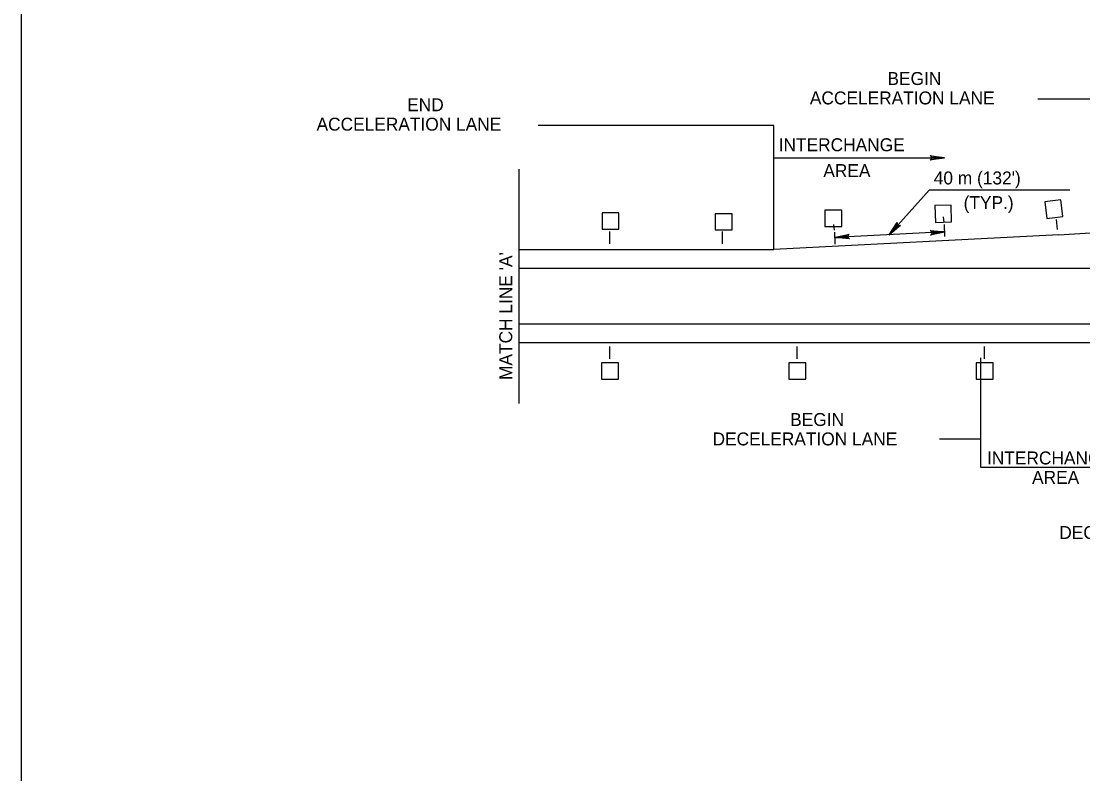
# Model space of a CAD drawing. Extents: x 640253 to 641999, y 298458 to 299646.
# Drawn here: x 641134.3 to 641380.3, y 299301.1 to 299475.5 of the extents above; entities that cross this region are included whole.
import ezdxf

# ---------------------------------------------------------------- set-up
doc = ezdxf.new("R2010")
doc.units = 0
doc.layers.add('1', color=7, linetype='Continuous')
doc.layers.add('2', color=7, linetype='Continuous')

msp = doc.modelspace()

# ---------------------------------------------------------------- linework, layer by layer
at = {"layer": '1'}
msp.add_line((641134.31, 299630.63), (641134.31, 299066.63), dxfattribs=at)
at = {"layer": '2'}
for p, q in [((641394.05, 299457.45), (641369.89, 299457.45)), ((641308.68, 299451.35), (641254.07, 299451.35)), ((641308.68, 299422.63), (641308.68, 299451.35)), ((641308.68, 299443.82), (641348.22, 299443.82)), ((641249.69, 299386.92), (641249.69, 299441.25)), ((641348.12, 299428.88), (641348.03, 299430.16)), ((641374.38, 299427.25), (641374.19, 299429.57)), ((641270.73, 299423.91), (641270.73, 299426.76)), ((641296.76, 299423.91), (641296.76, 299426.76)), ((641322.71, 299427.11), (641322.62, 299428.39)), ((641322.94, 299423.86), (641322.83, 299426.6)), ((641348.29, 299426.67), (641322.88, 299425.36)), ((641348.35, 299425.63), (641348.21, 299428.39)), ((641374.72, 299426.03), (641308.68, 299422.63)), ((641249.69, 299422.63), (641308.69, 299422.63)), ((641249.69, 299418.29), (641619.6, 299418.29)), ((641249.69, 299405.41), (641548.4, 299405.41)), ((641249.69, 299401.07), (641390.19, 299401.07)), ((641270.73, 299397.25), (641270.73, 299400.1)), ((641275.73, 299401.07), (641275.73, 299401.07)), ((641314.12, 299397.25), (641314.12, 299400.1)), ((641357.51, 299397.25), (641357.51, 299400.1)), ((641357.52, 299397.25), (641357.52, 299400.1)), ((641356.59, 299397.52), (641356.59, 299372.2)), ((641356.59, 299378.68), (641347.04, 299378.68)), ((641356.59, 299372.2), (641395.96, 299372.2))]:
    msp.add_line(p, q, dxfattribs=at)
for points in [[(641345.06, 299444.22), (641345.19, 299443.99), (641348.22, 299443.82), (641345.06, 299444.22), (641344.91, 299444.36), (641348.22, 299443.82), (641345.19, 299443.66), (641345.08, 299443.44), (641348.22, 299443.82), (641344.91, 299443.3), (641345.08, 299443.44)], [(641377.28, 299436.37), (641344.71, 299436.37), (641335.42, 299426.04)], [(641337.83, 299428.13), (641337.57, 299428.19), (641335.42, 299426.04), (641337.83, 299428.13), (641338.03, 299428.15), (641335.42, 299426.04), (641337.34, 299428.41), (641337.23, 299428.64), (641335.42, 299426.04), (641337.23, 299428.86), (641337.23, 299428.64)], [(641345.11, 299426.85), (641345.25, 299426.64), (641348.29, 299426.67), (641345.11, 299426.85), (641344.95, 299426.98), (641348.29, 299426.67), (641345.27, 299426.31), (641345.19, 299426.08), (641348.29, 299426.67), (641345.02, 299425.92), (641345.19, 299426.08)], [(641326.06, 299425.2), (641325.92, 299425.42), (641322.88, 299425.36), (641326.06, 299425.2), (641326.23, 299425.08), (641322.88, 299425.36), (641325.9, 299425.75), (641325.98, 299425.98), (641322.88, 299425.36), (641326.15, 299426.13), (641325.98, 299425.98)]]:
    msp.add_lwpolyline(points, dxfattribs=at)
for points in [[(641375.67, 299430.25), (641375.19, 299434.12), (641371.48, 299433.66), (641371.95, 299429.8)], [(641320.52, 299427.97), (641324.41, 299427.97), (641324.41, 299431.71), (641320.52, 299431.71)], [(641349.89, 299429.03), (641349.75, 299432.92), (641346, 299432.8), (641346.14, 299428.9)], [(641268.89, 299427.36), (641272.79, 299427.36), (641272.79, 299431.11), (641268.89, 299431.11)], [(641295.11, 299427.16), (641299, 299427.16), (641299, 299430.91), (641295.11, 299430.91)], [(641268.79, 299392.6), (641272.69, 299392.6), (641272.69, 299396.35), (641268.79, 299396.35)], [(641312.18, 299392.6), (641316.08, 299392.6), (641316.08, 299396.35), (641312.18, 299396.35)], [(641355.58, 299392.6), (641359.48, 299392.6), (641359.48, 299396.35), (641355.58, 299396.35)]]:
    msp.add_lwpolyline(points, close=True, dxfattribs=at)
msp.add_arc((641368.28, 299581), 155.1, 272.3776, 315.381, dxfattribs=at)

# ---------------------------------------------------------------- texts
for s, p in [('BEGIN', (641335.02, 299460.73)), ('ACCELERATION LANE', (641317.04, 299456.23)), ('END', (641223.73, 299454.65)), ('ACCELERATION LANE', (641202.74, 299450.15)), ('INTERCHANGE', (641309.81, 299445.38)), ('AREA', (641320.16, 299439.39)), ("40 m (132')", (641345.74, 299437.69)), ('(TYP.)', (641352.66, 299431.97)), ('BEGIN', (641312.48, 299381.72)), ('DECELERATION LANE', (641294.49, 299377.22)), ('INTERCHANGE', (641358.08, 299372.81)), ('AREA', (641368.52, 299368.31)), ('DECELERATION LANE', (641374.82, 299355.54))]:
    msp.add_text(s, height=3, dxfattribs=at).set_placement(p)
msp.add_text("MATCH LINE 'A'", height=3, rotation=90, dxfattribs=at).set_placement((641248.07, 299392.38))

doc.saveas('drawing.dxf')
